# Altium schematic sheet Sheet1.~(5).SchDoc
size A
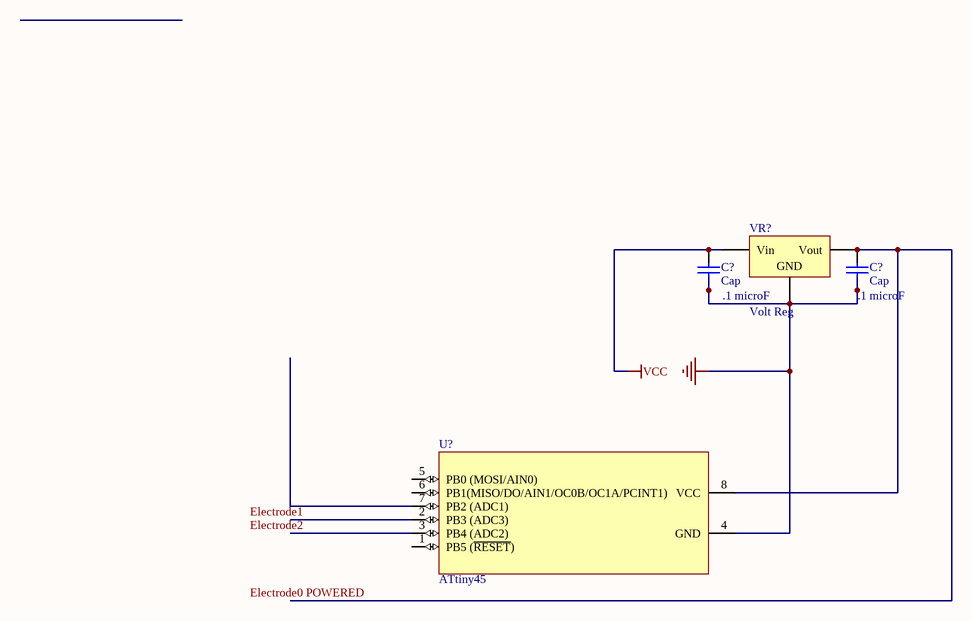
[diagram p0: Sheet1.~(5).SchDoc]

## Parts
(Parts that share a designator on the sheet are numbered #1, #2 ... from top to bottom, then left to right.)
C?#1  Cap  value .1 microF  [VP32-3.2]
C?#2  Cap  value .1 microF  [VP32-3.2]
U?  ATtiny45  [8S2_M]
VR?  Volt Reg  [SOT-23]

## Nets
GND: C?#1.1 C?#2.1 U?.4(GND) VR?.3(GND)
VCC: C?#1.2 VR?.2(Vin)
NetC?#2_2: C?#2.2 U?.8(VCC) VR?.1(Vout)

Not connected (* = marked no-connect by the designer): U? 1(PB5_(~{RESET})) 2(PB3_(ADC3)) 3(PB4_(ADC2)) 5(PB0_(MOSI/AIN0)) 6(PB1(MISO/DO/AIN1/OC0B/OC1A/PCINT1)) 7(PB2_(ADC1))

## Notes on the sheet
- Labels drawn without touching a wire or pin: Electrode0 POWERED, Electrode1, Electrode2

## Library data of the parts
C?#1 C?#2 = Cap: Capacitor
U? = ATtiny45: 8-Bit AVR Microcontroller with 1K Byte of Flash Memory
VR? = Volt Reg: Voltage Regulator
